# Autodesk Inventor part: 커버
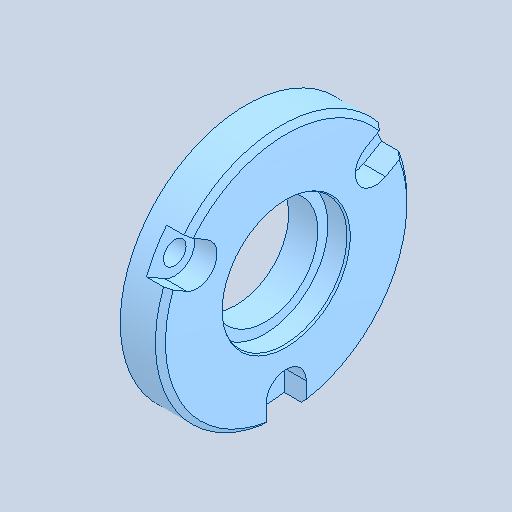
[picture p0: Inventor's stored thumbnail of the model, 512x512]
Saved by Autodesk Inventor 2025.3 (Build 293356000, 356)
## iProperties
Created: 2025-10
Part Number: 커버
Material: 알루미늄 6061
Document SubType Name: Modeling
Designer: USER
Density: 2.7 g/cm^3
Appearance: 기본값
Author: jhkim
Sending System: Autodesk Inventor 2026
Preprocessor: ST-DEVELOPER v20.1
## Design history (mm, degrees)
feature "솔리드1"
node "솔리드2"
